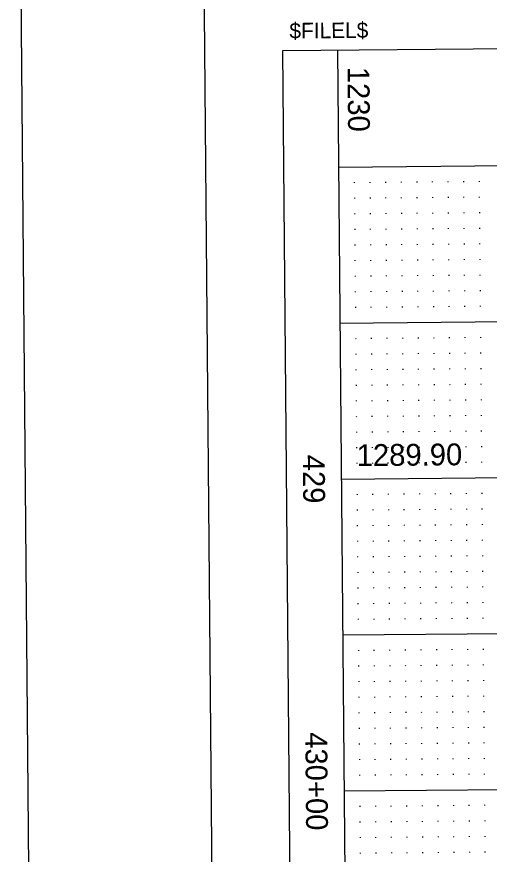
# Model space of a CAD drawing. Extents: x 2149873 to 2152007, y 140538 to 142349.
# Drawn here: x 2149872.9 to 2150024.4, y 141901.8 to 142170.3 of the extents above; entities that cross this region are included whole.
import ezdxf

# ---------------------------------------------------------------- set-up
doc = ezdxf.new("R2010")
doc.units = 0
for name, color, linetype in [('PR_Align_Ramp_M_Txt', 7, 'Continuous'), ('SHT_Plan_Profile_Sheet_Elev_Txt', 7, 'Continuous'), ('SHT_Plan_Profile_Sheet_Sta_Txt', 7, 'Continuous'), ('SHT_Plot_Shape_Full', 7, 'Continuous'), ('SHT_Plot_Shape_Half', 7, 'Continuous'), ('SHT_Plot_Stamp', 7, 'Continuous'), ('SHT_Profile_Grid_Major', 7, 'Continuous'), ('SHT_Profile_Grid_Minor', 7, 'Continuous'), ('SHT_Sheet_Border', 7, 'Continuous')]:
    doc.layers.add(name, color=color, linetype=linetype)

msp = doc.modelspace()

# ---------------------------------------------------------------- linework, layer by layer
at = {"layer": 'SHT_Plot_Shape_Full'}
msp.add_lwpolyline([(2151072.86, 142348.62), (2151088.62, 140548.69), (2149888.66, 140538.18), (2149872.91, 142338.11)], close=True, dxfattribs=at)
at = {"layer": 'SHT_Plot_Shape_Half'}
msp.add_lwpolyline([(2151032.33, 142266.38), (2151047.21, 140566.45), (2149947.25, 140556.82), (2149932.37, 142256.76)], close=True, dxfattribs=at)
at = {"layer": 'SHT_Profile_Grid_Major'}
for p, q in [((2149976.49, 142072.13), (2150476.47, 142076.51)), ((2149976.93, 142022.14), (2150476.91, 142026.51)), ((2149977.37, 141972.14), (2150477.35, 141976.51)), ((2149977.8, 141922.14), (2150477.79, 141926.52))]:
    msp.add_line(p, q, dxfattribs=at)
at = {"layer": 'SHT_Profile_Grid_Minor'}
for p, q in [((2149981.1, 142117.3), (2149981.1, 142117.05)), ((2149986.1, 142117.35), (2149986.1, 142117.1)), ((2149991.1, 142117.39), (2149991.1, 142117.14)), ((2149996.1, 142117.43), (2149996.1, 142117.18)), ((2150001.1, 142117.48), (2150001.1, 142117.23)), ((2150006.1, 142117.52), (2150006.1, 142117.27)), ((2150011.1, 142117.56), (2150011.1, 142117.31)), ((2150016.1, 142117.61), (2150016.1, 142117.36)), ((2150021.1, 142117.65), (2150021.1, 142117.4)), ((2149981.14, 142112.3), (2149981.14, 142112.05)), ((2149986.14, 142112.35), (2149986.14, 142112.1)), ((2149991.14, 142112.39), (2149991.14, 142112.14)), ((2149996.14, 142112.43), (2149996.14, 142112.18)), ((2150001.14, 142112.48), (2150001.14, 142112.23)), ((2150006.14, 142112.52), (2150006.14, 142112.27)), ((2150011.14, 142112.56), (2150011.14, 142112.31)), ((2150016.14, 142112.61), (2150016.14, 142112.36)), ((2150021.14, 142112.65), (2150021.14, 142112.4)), ((2149981.18, 142107.3), (2149981.19, 142107.05)), ((2149986.18, 142107.35), (2149986.19, 142107.1)), ((2149991.18, 142107.39), (2149991.19, 142107.14)), ((2149996.18, 142107.43), (2149996.19, 142107.18)), ((2150001.18, 142107.48), (2150001.19, 142107.23)), ((2150006.18, 142107.52), (2150006.19, 142107.27)), ((2150011.18, 142107.56), (2150011.19, 142107.31)), ((2150016.18, 142107.61), (2150016.19, 142107.36)), ((2150021.18, 142107.65), (2150021.18, 142107.4)), ((2149981.23, 142102.3), (2149981.23, 142102.05)), ((2149986.23, 142102.35), (2149986.23, 142102.1)), ((2149991.23, 142102.39), (2149991.23, 142102.14)), ((2149996.23, 142102.43), (2149996.23, 142102.18)), ((2150001.23, 142102.48), (2150001.23, 142102.23)), ((2150006.23, 142102.52), (2150006.23, 142102.27)), ((2150011.23, 142102.56), (2150011.23, 142102.31)), ((2150016.23, 142102.61), (2150016.23, 142102.36)), ((2150021.23, 142102.65), (2150021.23, 142102.4)), ((2149981.27, 142097.3), (2149981.27, 142097.05)), ((2149986.27, 142097.35), (2149986.27, 142097.1)), ((2149991.27, 142097.39), (2149991.27, 142097.14)), ((2149996.27, 142097.43), (2149996.27, 142097.18)), ((2150001.27, 142097.48), (2150001.27, 142097.23)), ((2150006.27, 142097.52), (2150006.27, 142097.27)), ((2150011.27, 142097.56), (2150011.27, 142097.31)), ((2150016.27, 142097.61), (2150016.27, 142097.36)), ((2150021.27, 142097.65), (2150021.27, 142097.4)), ((2149981.32, 142092.3), (2149981.32, 142092.05)), ((2149986.32, 142092.35), (2149986.32, 142092.1)), ((2149991.32, 142092.39), (2149991.32, 142092.14)), ((2149996.31, 142092.43), (2149996.32, 142092.18)), ((2150001.31, 142092.48), (2150001.32, 142092.23)), ((2150006.31, 142092.52), (2150006.32, 142092.27)), ((2150011.31, 142092.57), (2150011.32, 142092.32)), ((2150016.31, 142092.61), (2150016.32, 142092.36)), ((2150021.31, 142092.65), (2150021.32, 142092.4)), ((2149996.36, 142087.43), (2149996.36, 142087.18)), ((2150001.36, 142087.48), (2150001.36, 142087.23)), ((2150006.36, 142087.52), (2150006.36, 142087.27)), ((2150011.36, 142087.57), (2150011.36, 142087.32)), ((2150016.36, 142087.61), (2150016.36, 142087.36)), ((2150021.36, 142087.65), (2150021.36, 142087.4)), ((2149981.36, 142087.3), (2149981.36, 142087.05)), ((2149986.36, 142087.35), (2149986.36, 142087.1)), ((2149991.36, 142087.39), (2149991.36, 142087.14)), ((2149981.4, 142082.3), (2149981.41, 142082.05)), ((2149986.4, 142082.35), (2149986.41, 142082.1)), ((2149991.4, 142082.39), (2149991.4, 142082.14)), ((2149996.4, 142082.43), (2149996.4, 142082.18)), ((2150001.4, 142082.48), (2150001.4, 142082.23)), ((2150006.4, 142082.52), (2150006.4, 142082.27)), ((2150011.4, 142082.57), (2150011.4, 142082.32)), ((2150016.4, 142082.61), (2150016.4, 142082.36)), ((2150021.4, 142082.65), (2150021.4, 142082.4)), ((2149981.45, 142077.3), (2149981.45, 142077.05)), ((2149986.45, 142077.35), (2149986.45, 142077.1)), ((2149991.45, 142077.39), (2149991.45, 142077.14)), ((2149996.45, 142077.43), (2149996.45, 142077.18)), ((2150001.45, 142077.48), (2150001.45, 142077.23)), ((2150006.45, 142077.52), (2150006.45, 142077.27)), ((2150011.45, 142077.57), (2150011.45, 142077.32)), ((2150016.45, 142077.61), (2150016.45, 142077.36)), ((2150021.45, 142077.65), (2150021.45, 142077.4)), ((2149981.53, 142067.3), (2149981.54, 142067.05)), ((2149986.53, 142067.35), (2149986.54, 142067.1)), ((2149991.53, 142067.39), (2149991.54, 142067.14)), ((2149996.53, 142067.43), (2149996.54, 142067.18)), ((2150001.53, 142067.48), (2150001.54, 142067.23)), ((2150006.53, 142067.52), (2150006.54, 142067.27)), ((2150011.53, 142067.57), (2150011.54, 142067.32)), ((2150016.53, 142067.61), (2150016.54, 142067.36)), ((2150021.53, 142067.65), (2150021.53, 142067.4)), ((2149981.58, 142062.3), (2149981.58, 142062.05)), ((2149986.58, 142062.35), (2149986.58, 142062.1)), ((2149991.58, 142062.39), (2149991.58, 142062.14)), ((2149996.58, 142062.43), (2149996.58, 142062.18)), ((2150001.58, 142062.48), (2150001.58, 142062.23)), ((2150006.58, 142062.52), (2150006.58, 142062.27)), ((2150011.58, 142062.57), (2150011.58, 142062.32)), ((2150016.58, 142062.61), (2150016.58, 142062.36)), ((2150021.58, 142062.65), (2150021.58, 142062.4)), ((2149981.62, 142057.3), (2149981.62, 142057.05)), ((2149986.62, 142057.35), (2149986.62, 142057.1)), ((2149991.62, 142057.39), (2149991.62, 142057.14)), ((2149996.62, 142057.44), (2149996.62, 142057.19)), ((2150001.62, 142057.48), (2150001.62, 142057.23)), ((2150006.62, 142057.52), (2150006.62, 142057.27)), ((2150011.62, 142057.57), (2150011.62, 142057.32)), ((2150016.62, 142057.61), (2150016.62, 142057.36)), ((2150021.62, 142057.65), (2150021.62, 142057.4)), ((2150006.66, 142052.52), (2150006.67, 142052.27)), ((2150011.66, 142052.57), (2150011.67, 142052.32)), ((2150016.66, 142052.61), (2150016.67, 142052.36)), ((2150021.66, 142052.65), (2150021.67, 142052.4)), ((2149981.67, 142052.3), (2149981.67, 142052.05)), ((2149986.67, 142052.35), (2149986.67, 142052.1)), ((2149991.67, 142052.39), (2149991.67, 142052.14)), ((2149996.67, 142052.44), (2149996.67, 142052.19)), ((2150001.66, 142052.48), (2150001.67, 142052.23)), ((2149981.71, 142047.3), (2149981.71, 142047.05)), ((2149986.71, 142047.35), (2149986.71, 142047.1)), ((2149991.71, 142047.39), (2149991.71, 142047.14)), ((2149996.71, 142047.44), (2149996.71, 142047.19)), ((2150001.71, 142047.48), (2150001.71, 142047.23)), ((2150006.71, 142047.52), (2150006.71, 142047.27)), ((2150011.71, 142047.57), (2150011.71, 142047.32)), ((2150016.71, 142047.61), (2150016.71, 142047.36)), ((2150021.71, 142047.65), (2150021.71, 142047.4)), ((2149981.75, 142042.3), (2149981.76, 142042.05)), ((2149986.75, 142042.35), (2149986.76, 142042.1)), ((2149991.75, 142042.39), (2149991.75, 142042.14)), ((2149996.75, 142042.44), (2149996.75, 142042.19)), ((2150001.75, 142042.48), (2150001.75, 142042.23)), ((2150006.75, 142042.52), (2150006.75, 142042.27)), ((2150011.75, 142042.57), (2150011.75, 142042.32)), ((2150016.75, 142042.61), (2150016.75, 142042.36)), ((2150021.75, 142042.65), (2150021.75, 142042.4)), ((2149981.8, 142037.3), (2149981.8, 142037.05)), ((2149986.8, 142037.35), (2149986.8, 142037.1)), ((2149991.8, 142037.39), (2149991.8, 142037.14)), ((2149996.8, 142037.44), (2149996.8, 142037.19)), ((2150001.8, 142037.48), (2150001.8, 142037.23)), ((2150006.8, 142037.52), (2150006.8, 142037.27)), ((2150011.8, 142037.57), (2150011.8, 142037.32)), ((2150016.8, 142037.61), (2150016.8, 142037.36)), ((2150021.8, 142037.65), (2150021.8, 142037.4)), ((2149981.84, 142032.3), (2149981.84, 142032.05)), ((2149986.84, 142032.35), (2149986.84, 142032.1)), ((2149991.84, 142032.39), (2149991.84, 142032.14)), ((2149996.84, 142032.44), (2149996.84, 142032.19)), ((2150001.84, 142032.48), (2150001.84, 142032.23)), ((2150006.84, 142032.52), (2150006.84, 142032.27)), ((2150011.84, 142032.57), (2150011.84, 142032.32)), ((2150016.84, 142032.61), (2150016.84, 142032.36)), ((2150021.84, 142032.65), (2150021.84, 142032.4)), ((2149981.88, 142027.31), (2149981.89, 142027.06)), ((2149986.88, 142027.35), (2149986.89, 142027.1)), ((2149991.88, 142027.39), (2149991.89, 142027.14)), ((2149996.88, 142027.44), (2149996.89, 142027.19)), ((2150001.88, 142027.48), (2150001.89, 142027.23)), ((2150006.88, 142027.52), (2150006.89, 142027.27)), ((2150011.88, 142027.57), (2150011.89, 142027.32)), ((2150016.88, 142027.61), (2150016.89, 142027.36)), ((2150021.88, 142027.66), (2150021.89, 142027.41)), ((2150016.97, 142017.61), (2150016.97, 142017.36)), ((2150021.97, 142017.66), (2150021.97, 142017.41)), ((2149981.97, 142017.31), (2149981.97, 142017.06)), ((2149986.97, 142017.35), (2149986.97, 142017.1)), ((2149991.97, 142017.39), (2149991.97, 142017.14)), ((2149996.97, 142017.44), (2149996.97, 142017.19)), ((2150001.97, 142017.48), (2150001.97, 142017.23)), ((2150006.97, 142017.52), (2150006.97, 142017.27)), ((2150011.97, 142017.57), (2150011.97, 142017.32)), ((2149982.02, 142012.31), (2149982.02, 142012.06)), ((2149987.02, 142012.35), (2149987.02, 142012.1)), ((2149992.02, 142012.39), (2149992.02, 142012.14)), ((2149997.02, 142012.44), (2149997.02, 142012.19)), ((2150002.01, 142012.48), (2150002.02, 142012.23)), ((2150007.01, 142012.52), (2150007.02, 142012.27)), ((2150012.01, 142012.57), (2150012.02, 142012.32)), ((2150017.01, 142012.61), (2150017.02, 142012.36)), ((2150022.01, 142012.66), (2150022.02, 142012.41)), ((2149982.06, 142007.31), (2149982.06, 142007.06)), ((2149987.06, 142007.35), (2149987.06, 142007.1)), ((2149992.06, 142007.39), (2149992.06, 142007.14)), ((2149997.06, 142007.44), (2149997.06, 142007.19)), ((2150002.06, 142007.48), (2150002.06, 142007.23)), ((2150007.06, 142007.52), (2150007.06, 142007.27)), ((2150012.06, 142007.57), (2150012.06, 142007.32)), ((2150017.06, 142007.61), (2150017.06, 142007.36)), ((2150022.06, 142007.66), (2150022.06, 142007.41)), ((2149982.1, 142002.31), (2149982.11, 142002.06)), ((2149987.1, 142002.35), (2149987.11, 142002.1)), ((2149992.1, 142002.39), (2149992.11, 142002.14)), ((2149997.1, 142002.44), (2149997.1, 142002.19)), ((2150002.1, 142002.48), (2150002.1, 142002.23)), ((2150007.1, 142002.52), (2150007.1, 142002.27)), ((2150012.1, 142002.57), (2150012.1, 142002.32)), ((2150017.1, 142002.61), (2150017.1, 142002.36)), ((2150022.1, 142002.66), (2150022.1, 142002.41)), ((2149982.15, 141997.31), (2149982.15, 141997.06)), ((2149987.15, 141997.35), (2149987.15, 141997.1)), ((2149992.15, 141997.39), (2149992.15, 141997.14)), ((2149997.15, 141997.44), (2149997.15, 141997.19)), ((2150002.15, 141997.48), (2150002.15, 141997.23)), ((2150007.15, 141997.52), (2150007.15, 141997.27)), ((2150012.15, 141997.57), (2150012.15, 141997.32)), ((2150017.15, 141997.61), (2150017.15, 141997.36)), ((2150022.15, 141997.66), (2150022.15, 141997.41)), ((2149982.19, 141992.31), (2149982.19, 141992.06)), ((2149987.19, 141992.35), (2149987.19, 141992.1)), ((2149992.19, 141992.39), (2149992.19, 141992.14)), ((2149997.19, 141992.44), (2149997.19, 141992.19)), ((2150002.19, 141992.48), (2150002.19, 141992.23)), ((2150007.19, 141992.53), (2150007.19, 141992.28)), ((2150012.19, 141992.57), (2150012.19, 141992.32)), ((2150017.19, 141992.61), (2150017.19, 141992.36)), ((2150022.19, 141992.66), (2150022.19, 141992.41)), ((2149982.23, 141987.31), (2149982.24, 141987.06)), ((2149987.23, 141987.35), (2149987.24, 141987.1)), ((2149992.23, 141987.39), (2149992.24, 141987.14)), ((2149997.23, 141987.44), (2149997.24, 141987.19)), ((2150002.23, 141987.48), (2150002.24, 141987.23)), ((2150007.23, 141987.53), (2150007.24, 141987.28)), ((2150012.23, 141987.57), (2150012.24, 141987.32)), ((2150017.23, 141987.61), (2150017.24, 141987.36)), ((2150022.23, 141987.66), (2150022.24, 141987.41)), ((2149982.28, 141982.31), (2149982.28, 141982.06)), ((2149987.28, 141982.35), (2149987.28, 141982.1)), ((2149992.28, 141982.39), (2149992.28, 141982.14)), ((2149997.28, 141982.44), (2149997.28, 141982.19)), ((2150002.28, 141982.48), (2150002.28, 141982.23)), ((2150007.28, 141982.53), (2150007.28, 141982.28)), ((2150012.28, 141982.57), (2150012.28, 141982.32)), ((2150017.28, 141982.61), (2150017.28, 141982.36)), ((2150022.28, 141982.66), (2150022.28, 141982.41)), ((2149987.32, 141977.35), (2149987.32, 141977.1)), ((2149992.32, 141977.39), (2149992.32, 141977.14)), ((2149997.32, 141977.44), (2149997.32, 141977.19)), ((2150002.32, 141977.48), (2150002.32, 141977.23)), ((2150007.32, 141977.53), (2150007.32, 141977.28)), ((2150012.32, 141977.57), (2150012.32, 141977.32)), ((2150017.32, 141977.61), (2150017.32, 141977.36)), ((2150022.32, 141977.66), (2150022.32, 141977.41)), ((2149982.32, 141977.31), (2149982.32, 141977.06)), ((2149982.41, 141967.31), (2149982.41, 141967.06)), ((2149987.41, 141967.35), (2149987.41, 141967.1)), ((2149992.41, 141967.39), (2149992.41, 141967.14)), ((2149997.41, 141967.44), (2149997.41, 141967.19)), ((2150002.41, 141967.48), (2150002.41, 141967.23)), ((2150007.41, 141967.53), (2150007.41, 141967.28)), ((2150012.41, 141967.57), (2150012.41, 141967.32)), ((2150017.41, 141967.61), (2150017.41, 141967.36)), ((2150022.41, 141967.66), (2150022.41, 141967.41)), ((2149982.45, 141962.31), (2149982.46, 141962.06)), ((2149987.45, 141962.35), (2149987.46, 141962.1)), ((2149992.45, 141962.39), (2149992.46, 141962.14)), ((2149997.45, 141962.44), (2149997.46, 141962.19)), ((2150002.45, 141962.48), (2150002.45, 141962.23)), ((2150007.45, 141962.53), (2150007.45, 141962.28)), ((2150012.45, 141962.57), (2150012.45, 141962.32)), ((2150017.45, 141962.61), (2150017.45, 141962.36)), ((2150022.45, 141962.66), (2150022.45, 141962.41)), ((2149982.5, 141957.31), (2149982.5, 141957.06)), ((2149987.5, 141957.35), (2149987.5, 141957.1)), ((2149992.5, 141957.4), (2149992.5, 141957.15)), ((2149997.5, 141957.44), (2149997.5, 141957.19)), ((2150002.5, 141957.48), (2150002.5, 141957.23)), ((2150007.5, 141957.53), (2150007.5, 141957.28)), ((2150012.5, 141957.57), (2150012.5, 141957.32)), ((2150017.5, 141957.61), (2150017.5, 141957.36)), ((2150022.5, 141957.66), (2150022.5, 141957.41)), ((2149982.54, 141952.31), (2149982.54, 141952.06)), ((2149987.54, 141952.35), (2149987.54, 141952.1)), ((2149992.54, 141952.4), (2149992.54, 141952.15)), ((2149997.54, 141952.44), (2149997.54, 141952.19)), ((2150002.54, 141952.48), (2150002.54, 141952.23)), ((2150007.54, 141952.53), (2150007.54, 141952.28)), ((2150012.54, 141952.57), (2150012.54, 141952.32)), ((2150017.54, 141952.61), (2150017.54, 141952.36)), ((2150022.54, 141952.66), (2150022.54, 141952.41)), ((2149982.58, 141947.31), (2149982.59, 141947.06)), ((2149987.58, 141947.35), (2149987.59, 141947.1)), ((2149992.58, 141947.4), (2149992.59, 141947.15)), ((2149997.58, 141947.44), (2149997.59, 141947.19)), ((2150002.58, 141947.48), (2150002.59, 141947.23)), ((2150007.58, 141947.53), (2150007.59, 141947.28)), ((2150012.58, 141947.57), (2150012.59, 141947.32)), ((2150017.58, 141947.61), (2150017.59, 141947.36)), ((2150022.58, 141947.66), (2150022.59, 141947.41)), ((2149997.63, 141942.44), (2149997.63, 141942.19)), ((2150002.63, 141942.48), (2150002.63, 141942.23)), ((2150007.63, 141942.53), (2150007.63, 141942.28)), ((2150012.63, 141942.57), (2150012.63, 141942.32)), ((2150017.63, 141942.61), (2150017.63, 141942.36)), ((2150022.63, 141942.66), (2150022.63, 141942.41)), ((2149982.63, 141942.31), (2149982.63, 141942.06)), ((2149987.63, 141942.35), (2149987.63, 141942.1)), ((2149992.63, 141942.4), (2149992.63, 141942.15)), ((2149982.67, 141937.31), (2149982.67, 141937.06)), ((2149987.67, 141937.35), (2149987.67, 141937.1)), ((2149992.67, 141937.4), (2149992.67, 141937.15)), ((2149997.67, 141937.44), (2149997.67, 141937.19)), ((2150002.67, 141937.48), (2150002.67, 141937.23)), ((2150007.67, 141937.53), (2150007.67, 141937.28)), ((2150012.67, 141937.57), (2150012.67, 141937.32)), ((2150017.67, 141937.61), (2150017.67, 141937.36)), ((2150022.67, 141937.66), (2150022.67, 141937.41)), ((2149982.72, 141932.31), (2149982.72, 141932.06)), ((2149987.72, 141932.35), (2149987.72, 141932.1)), ((2149992.72, 141932.4), (2149992.72, 141932.15)), ((2149997.72, 141932.44), (2149997.72, 141932.19)), ((2150002.72, 141932.48), (2150002.72, 141932.23)), ((2150007.72, 141932.53), (2150007.72, 141932.28)), ((2150012.71, 141932.57), (2150012.72, 141932.32)), ((2150017.71, 141932.61), (2150017.72, 141932.37)), ((2150022.71, 141932.66), (2150022.72, 141932.41)), ((2149982.76, 141927.31), (2149982.76, 141927.06)), ((2149987.76, 141927.35), (2149987.76, 141927.1)), ((2149992.76, 141927.4), (2149992.76, 141927.15)), ((2149997.76, 141927.44), (2149997.76, 141927.19)), ((2150002.76, 141927.48), (2150002.76, 141927.23)), ((2150007.76, 141927.53), (2150007.76, 141927.28)), ((2150012.76, 141927.57), (2150012.76, 141927.32)), ((2150017.76, 141927.62), (2150017.76, 141927.37)), ((2150022.76, 141927.66), (2150022.76, 141927.41)), ((2149982.85, 141917.31), (2149982.85, 141917.06)), ((2149987.85, 141917.35), (2149987.85, 141917.1)), ((2149992.85, 141917.4), (2149992.85, 141917.15)), ((2149997.85, 141917.44), (2149997.85, 141917.19)), ((2150002.85, 141917.48), (2150002.85, 141917.23)), ((2150007.85, 141917.53), (2150007.85, 141917.28)), ((2150012.85, 141917.57), (2150012.85, 141917.32)), ((2150017.85, 141917.62), (2150017.85, 141917.37)), ((2150022.85, 141917.66), (2150022.85, 141917.41)), ((2149982.89, 141912.31), (2149982.89, 141912.06)), ((2149987.89, 141912.35), (2149987.89, 141912.1)), ((2149992.89, 141912.4), (2149992.89, 141912.15)), ((2149997.89, 141912.44), (2149997.89, 141912.19)), ((2150002.89, 141912.48), (2150002.89, 141912.23)), ((2150007.89, 141912.53), (2150007.89, 141912.28)), ((2150012.89, 141912.57), (2150012.89, 141912.32)), ((2150017.89, 141912.62), (2150017.89, 141912.37)), ((2150022.89, 141912.66), (2150022.89, 141912.41)), ((2150007.93, 141907.53), (2150007.94, 141907.28)), ((2150012.93, 141907.57), (2150012.94, 141907.32)), ((2150017.93, 141907.62), (2150017.94, 141907.37)), ((2150022.93, 141907.66), (2150022.94, 141907.41)), ((2149982.93, 141907.31), (2149982.94, 141907.06)), ((2149987.93, 141907.35), (2149987.94, 141907.1)), ((2149992.93, 141907.4), (2149992.94, 141907.15)), ((2149997.93, 141907.44), (2149997.94, 141907.19)), ((2150002.93, 141907.48), (2150002.94, 141907.23)), ((2149982.98, 141902.31), (2149982.98, 141902.06)), ((2149987.98, 141902.35), (2149987.98, 141902.1)), ((2149992.98, 141902.4), (2149992.98, 141902.15)), ((2149997.98, 141902.44), (2149997.98, 141902.19)), ((2150002.98, 141902.48), (2150002.98, 141902.23)), ((2150007.98, 141902.53), (2150007.98, 141902.28)), ((2150012.98, 141902.57), (2150012.98, 141902.32)), ((2150017.98, 141902.62), (2150017.98, 141902.37)), ((2150022.98, 141902.66), (2150022.98, 141902.41))]:
    msp.add_line(p, q, dxfattribs=at)
at = {"layer": 'SHT_Sheet_Border'}
for p, q in [((2149975.73, 142159.63), (2149987.21, 140847.18)), ((2149976.05, 142122.13), (2150476.04, 142126.51))]:
    msp.add_line(p, q, dxfattribs=at)
msp.add_lwpolyline([(2151008.19, 142168.67), (2151021.97, 140593.73), (2149972.01, 140584.54), (2149958.23, 142159.48)], close=True, dxfattribs=at)

# ---------------------------------------------------------------- texts
at = {"layer": 'PR_Align_Ramp_M_Txt'}
msp.add_text('1289.90', height=7, rotation=0.5015, dxfattribs=at).set_placement((2149981.89, 142026.26))
at = {"layer": 'SHT_Plan_Profile_Sheet_Elev_Txt'}
msp.add_text('1230', height=7, rotation=270.5015, dxfattribs=at).set_placement((2149978.93, 142154.26))
at = {"layer": 'SHT_Plan_Profile_Sheet_Sta_Txt'}
for s, p in [('429', (2149964.61, 142029.89)), ('430+00', (2149965.39, 141940.93))]:
    msp.add_text(s, height=7, rotation=270.5015, dxfattribs=at).set_placement(p)
at = {"layer": 'SHT_Plot_Stamp'}
msp.add_text('$FILEL$', height=5, rotation=0.5015, dxfattribs=at).set_placement((2149960.32, 142163.36))

doc.saveas('drawing.dxf')
